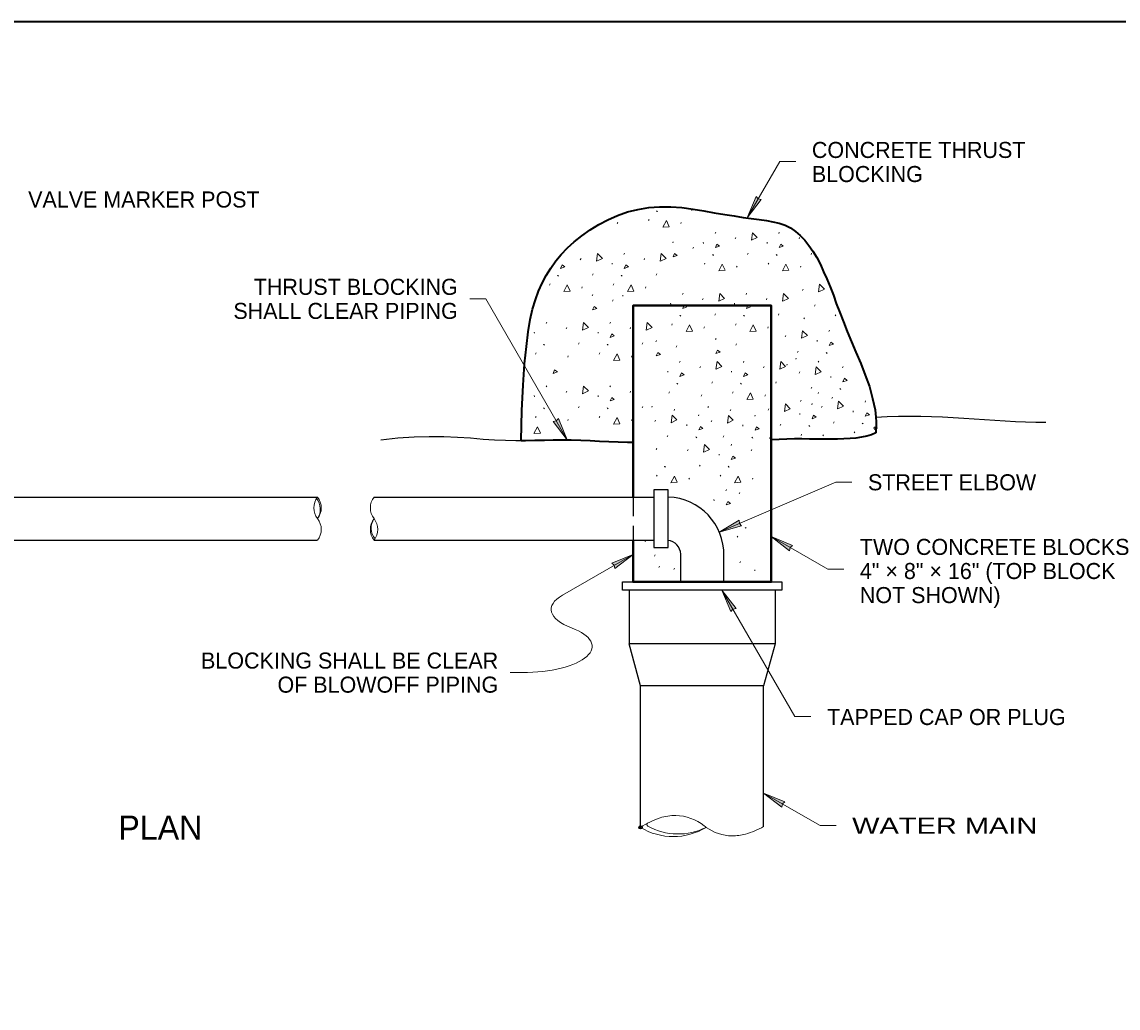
# Model space of a CAD drawing. Extents: x 99860 to 103153, y 99998 to 102077.
# Drawn here: x 100960 to 102052, y 101093 to 102076 of the extents above; entities that cross this region are included whole.
import ezdxf
from ezdxf.enums import TextEntityAlignment as Align

# ---------------------------------------------------------------- set-up
doc = ezdxf.new("R2010")
doc.units = 0
doc.header["$LTSCALE"] = 6.4
doc.header["$PDMODE"] = 32
doc.header["$PDSIZE"] = 3.2
doc.linetypes.add('MEDIUM_DASHED', pattern=[4.5, 3, -1.5])
for name, color, linetype, lineweight in [('1', 7, 'Continuous', 13), ('10', 7, 'Continuous', 13), ('11', 7, 'Continuous', 13), ('14', 7, 'Continuous', 13), ('15', 7, 'Continuous', 13), ('17', 7, 'Continuous', 35), ('20', 7, 'Continuous', 13), ('6', 7, 'Continuous', 25)]:
    doc.layers.add(name, color=color, linetype=linetype, lineweight=lineweight)

msp = doc.modelspace()

# ---------------------------------------------------------------- hatches: boundary and pattern name
at = {"layer": '15'}
for points in [[(101682.738, 101880.169), (101696.737, 101898.447), (101693.623, 101899.023), (101691.567, 101901.432)], [(101503.421, 101659.019), (101494.591, 101680.282), (101492.534, 101677.875), (101489.421, 101677.297)], [(101654.935, 101567.093), (101677.104, 101573.307), (101674.961, 101575.638), (101674.761, 101578.798)], [(101706.748, 101562.481), (101728.011, 101553.651), (101725.604, 101551.594), (101725.026, 101548.481)], [(101569.028, 101544.809), (101547.765, 101535.979), (101550.172, 101533.922), (101550.75, 101530.809)], [(101657.637, 101509.057), (101671.636, 101490.779), (101668.522, 101490.203), (101666.466, 101487.794)], [(101699.038, 101306.944), (101720.301, 101298.114), (101717.894, 101296.057), (101717.316, 101292.944)]]:
    msp.add_hatch(color=256, dxfattribs=at).paths.add_polyline_path(points)

# ---------------------------------------------------------------- linework, layer by layer
at = {"layer": '1'}
for p, q in [((101592.401, 101887.257), (101592.963, 101886.532)), ((101592.963, 101886.969), (101593.413, 101886.282)), ((101627.513, 101887.257), (101627.926, 101888.557)), ((101553.176, 101874.469), (101553.751, 101875.607)), ((101584.563, 101877.444), (101585.138, 101878.569)), ((101616.713, 101874.469), (101617.126, 101875.607)), ((101650.788, 101864.582), (101651.351, 101865.844)), ((101670.838, 101859.182), (101671.563, 101860.482)), ((101714.313, 101864.582), (101714.763, 101865.844)), ((101734.501, 101859.182), (101734.901, 101860.482)), ((101608.563, 101855.207), (101609.138, 101856.469)), ((101628.613, 101849.807), (101629.338, 101851.107)), ((101639.001, 101855.932), (101639.163, 101854.794)), ((101702.513, 101855.932), (101702.513, 101854.794)), ((101516.426, 101838.382), (101517.151, 101839.669)), ((101548.088, 101835.119), (101548.088, 101833.982)), ((101559.901, 101843.782), (101560.351, 101845.044)), ((101580.088, 101838.382), (101580.488, 101839.669)), ((101640.138, 101834.019), (101640.713, 101835.157)), ((101648.101, 101843.844), (101648.513, 101843.119)), ((101648.513, 101843.557), (101649.076, 101842.857)), ((101682.926, 101843.844), (101683.626, 101845.132)), ((101703.651, 101834.019), (101704.213, 101835.157)), ((101711.476, 101843.844), (101712.038, 101843.119)), ((101712.038, 101843.557), (101712.488, 101842.857)), ((101746.588, 101843.844), (101747.001, 101845.132)), ((101528.513, 101823.032), (101529.213, 101824.319)), ((101592.176, 101823.032), (101592.588, 101824.319)), ((101672.251, 101831.057), (101672.826, 101832.182)), ((101735.788, 101831.057), (101736.201, 101832.182)), ((101485.726, 101813.207), (101486.301, 101814.344)), ((101493.688, 101823.032), (101494.101, 101822.307)), ((101494.101, 101822.744), (101494.663, 101822.057)), ((101549.226, 101813.207), (101549.801, 101814.344)), ((101557.063, 101823.032), (101557.626, 101822.307)), ((101557.626, 101822.744), (101558.076, 101822.057)), ((101517.838, 101810.244), (101518.413, 101811.382)), ((101528.388, 101802.507), (101528.963, 101803.769)), ((101558.826, 101803.232), (101558.988, 101802.094)), ((101581.376, 101810.244), (101581.788, 101811.382)), ((101618.226, 101803.957), (101618.801, 101805.219)), ((101681.763, 101803.957), (101682.201, 101805.219)), ((101737.751, 101807.719), (101738.476, 101809.007)), ((101548.438, 101797.107), (101549.163, 101798.394)), ((101606.451, 101795.307), (101606.613, 101794.169)), ((101638.276, 101798.557), (101639.001, 101799.857)), ((101669.951, 101795.307), (101669.951, 101794.169)), ((101701.938, 101798.557), (101702.351, 101799.857)), ((101749.838, 101792.369), (101750.538, 101793.669)), ((101615.538, 101783.207), (101615.951, 101782.482)), ((101615.951, 101782.932), (101616.526, 101782.232)), ((101650.376, 101783.207), (101651.063, 101784.507)), ((101678.926, 101783.207), (101679.488, 101782.482)), ((101679.488, 101782.932), (101679.926, 101782.232)), ((101714.038, 101783.207), (101714.438, 101784.507)), ((101739.163, 101779.582), (101739.738, 101780.719)), ((101770.563, 101782.544), (101771.126, 101783.682)), ((101482.413, 101775.032), (101482.976, 101776.294)), ((101502.463, 101769.632), (101503.188, 101770.932)), ((101545.951, 101775.032), (101546.388, 101776.294)), ((101566.126, 101769.632), (101566.538, 101770.932)), ((101607.588, 101773.394), (101608.151, 101774.532)), ((101639.701, 101770.419), (101640.263, 101771.557)), ((101671.088, 101773.394), (101671.651, 101774.532)), ((101703.238, 101770.419), (101703.651, 101771.557)), ((101470.638, 101766.382), (101470.788, 101765.244)), ((101534.138, 101766.382), (101534.138, 101765.244)), ((101651.263, 101758.832), (101651.826, 101760.094)), ((101720.701, 101761.519), (101721.426, 101762.807)), ((101764.176, 101766.919), (101764.626, 101768.182)), ((101479.726, 101754.282), (101480.138, 101753.557)), ((101480.138, 101754.007), (101480.713, 101753.307)), ((101514.563, 101754.282), (101515.251, 101755.582)), ((101543.101, 101754.282), (101543.676, 101753.557)), ((101543.676, 101754.007), (101544.113, 101753.307)), ((101578.213, 101754.282), (101578.626, 101755.582)), ((101591.863, 101756.682), (101592.426, 101757.944)), ((101611.913, 101751.282), (101612.638, 101752.582)), ((101671.313, 101753.432), (101672.038, 101754.732)), ((101752.363, 101758.269), (101752.363, 101757.132)), ((101471.776, 101744.469), (101472.338, 101745.607)), ((101503.888, 101741.494), (101504.451, 101742.632)), ((101535.276, 101744.469), (101535.838, 101745.607)), ((101567.413, 101741.494), (101567.826, 101742.632)), ((101615.413, 101736.132), (101615.988, 101737.394)), ((101678.951, 101736.132), (101679.388, 101737.394)), ((101731.213, 101739.419), (101731.626, 101740.544)), ((101732.788, 101746.169), (101733.488, 101747.469)), ((101753.501, 101736.344), (101754.076, 101737.482)), ((101761.338, 101746.169), (101761.901, 101745.444)), ((101761.901, 101745.882), (101762.351, 101745.194)), ((101603.638, 101727.482), (101603.801, 101726.344)), ((101635.463, 101730.732), (101636.201, 101732.019)), ((101667.138, 101727.482), (101667.138, 101726.344)), ((101699.126, 101730.732), (101699.538, 101732.019)), ((101722.113, 101733.382), (101722.688, 101734.519)), ((101734.401, 101725.394), (101735.126, 101726.682)), ((101777.888, 101730.794), (101778.326, 101732.057)), ((101612.738, 101715.382), (101613.138, 101714.657)), ((101613.138, 101715.094), (101613.713, 101714.407)), ((101647.563, 101715.382), (101648.263, 101716.682)), ((101676.113, 101715.382), (101676.676, 101714.657)), ((101676.676, 101715.094), (101677.126, 101714.407)), ((101711.226, 101715.382), (101711.638, 101716.682)), ((101766.076, 101722.144), (101766.076, 101721.007)), ((101482.413, 101711.694), (101482.976, 101712.957)), ((101502.463, 101706.294), (101503.188, 101707.582)), ((101545.951, 101711.694), (101546.388, 101712.957)), ((101566.126, 101706.294), (101566.538, 101707.582)), ((101604.776, 101705.557), (101605.338, 101706.694)), ((101668.276, 101705.557), (101668.851, 101706.694)), ((101746.501, 101710.044), (101747.188, 101711.344)), ((101753.501, 101705.119), (101753.913, 101706.257)), ((101775.038, 101710.044), (101775.613, 101709.319)), ((101775.613, 101709.757), (101776.051, 101709.069)), ((101470.638, 101703.032), (101470.788, 101701.894)), ((101534.138, 101703.032), (101534.138, 101701.894)), ((101636.888, 101702.594), (101637.463, 101703.732)), ((101700.426, 101702.594), (101700.838, 101703.732)), ((101735.826, 101697.257), (101736.388, 101698.394)), ((101747.101, 101693.969), (101747.538, 101695.232)), ((101767.213, 101700.219), (101767.776, 101701.357)), ((101800.176, 101696.494), (101800.613, 101697.757)), ((101471.776, 101681.119), (101472.338, 101682.257)), ((101479.726, 101690.944), (101480.138, 101690.219)), ((101480.138, 101690.657), (101480.713, 101689.957)), ((101514.563, 101690.944), (101515.251, 101692.232)), ((101535.276, 101681.119), (101535.838, 101682.257)), ((101543.101, 101690.944), (101543.676, 101690.219)), ((101543.676, 101690.657), (101544.113, 101689.957)), ((101578.213, 101690.944), (101578.626, 101692.232)), ((101587.601, 101691.419), (101588.013, 101692.557)), ((101609.888, 101688.357), (101610.463, 101689.494)), ((101634.263, 101682.794), (101634.713, 101684.057)), ((101643.651, 101691.069), (101644.063, 101692.207)), ((101665.938, 101688.007), (101666.513, 101689.144)), ((101690.313, 101682.444), (101690.763, 101683.707)), ((101703.613, 101688.569), (101704.338, 101689.869)), ((101735.288, 101685.319), (101735.288, 101684.182)), ((101756.701, 101691.094), (101757.426, 101692.394)), ((101788.363, 101687.844), (101788.363, 101686.707)), ((101503.888, 101678.157), (101504.451, 101679.294)), ((101567.413, 101678.157), (101567.826, 101679.294)), ((101590.788, 101677.394), (101591.513, 101678.694)), ((101622.463, 101674.144), (101622.463, 101673.007)), ((101646.838, 101677.044), (101647.563, 101678.344)), ((101678.513, 101673.794), (101678.513, 101672.657)), ((101715.713, 101673.232), (101716.401, 101674.519)), ((101744.251, 101673.232), (101744.826, 101672.494)), ((101744.826, 101672.944), (101745.263, 101672.244)), ((101768.788, 101675.757), (101769.488, 101677.044)), ((101797.338, 101675.757), (101797.901, 101675.032)), ((101797.901, 101675.469), (101798.351, 101674.769)), ((101602.876, 101662.044), (101603.576, 101663.344)), ((101631.426, 101662.044), (101632.001, 101661.319)), ((101632.001, 101661.769), (101632.438, 101661.069)), ((101658.926, 101661.707), (101659.626, 101662.994)), ((101687.476, 101661.707), (101688.051, 101660.969)), ((101688.051, 101661.419), (101688.488, 101660.719)), ((101705.038, 101660.432), (101705.601, 101661.569)), ((101736.426, 101663.407), (101736.988, 101664.544)), ((101758.113, 101662.969), (101758.688, 101664.107)), ((101789.501, 101665.932), (101790.076, 101667.069)), ((101592.213, 101649.257), (101592.776, 101650.394)), ((101666.638, 101653.332), (101667.076, 101654.594)), ((101623.151, 101647.932), (101623.876, 101649.232)), ((101654.826, 101644.682), (101654.826, 101643.544)), ((101686.813, 101647.932), (101687.226, 101649.232)), ((101600.413, 101632.582), (101600.826, 101631.857)), ((101600.826, 101632.307), (101601.401, 101631.607)), ((101635.251, 101632.582), (101635.938, 101633.882)), ((101663.788, 101632.582), (101664.363, 101631.857)), ((101664.363, 101632.307), (101664.801, 101631.607)), ((101592.463, 101622.769), (101593.026, 101623.907)), ((101624.576, 101619.794), (101625.138, 101620.932)), ((101655.963, 101622.769), (101656.526, 101623.907)), ((101688.113, 101619.794), (101688.513, 101620.932)), ((101661.463, 101608.119), (101662.026, 101609.382)), ((101674.726, 101605.144), (101675.288, 101606.407)), ((101649.676, 101599.457), (101649.838, 101598.319)), ((101672.788, 101561.944), (101673.363, 101563.082)), ((101680.751, 101571.769), (101681.163, 101571.044)), ((101681.163, 101571.482), (101681.726, 101570.794)), ((101590.251, 101543.007), (101590.951, 101544.294)), ((101594.551, 101531.882), (101595.238, 101533.182)), ((101609.538, 101529.807), (101610.238, 101531.094)), ((101675.351, 101536.432), (101675.926, 101537.569)), ((101690.251, 101529.582), (101690.413, 101528.444))]:
    msp.add_line(p, q, dxfattribs=at)
at = {"layer": '1', "lineweight": 25}
msp.add_line((101581.413, 101557.557), (101581.413, 101558.919), dxfattribs=at)
at = {"layer": '1', "lineweight": 35}
msp.add_lwpolyline([(99862, 99999.5), (103151, 99999.5), (103151, 102075.5), (99862, 102075.5)], close=True, dxfattribs=at)
at = {"layer": '1'}
for points in [[(101598.776, 101870.932), (101602.338, 101877.594), (101605.026, 101871.344), (101598.938, 101870.932)], [(101687.038, 101857.894), (101688.051, 101865.444), (101692.851, 101860.607), (101687.163, 101857.894)], [(101532.626, 101837.082), (101533.626, 101844.632), (101538.426, 101839.794), (101532.751, 101837.082)], [(101596.151, 101837.082), (101597.138, 101844.632), (101601.963, 101839.794), (101596.276, 101837.082)], [(101654.351, 101827.519), (101657.926, 101834.182), (101660.763, 101827.919), (101654.513, 101827.519)], [(101717.851, 101827.519), (101721.426, 101834.182), (101724.113, 101827.919), (101718.013, 101827.519)], [(101499.938, 101806.707), (101503.501, 101813.369), (101506.351, 101807.119), (101500.101, 101806.707)], [(101563.438, 101806.707), (101567.013, 101813.369), (101569.688, 101807.119), (101563.601, 101806.707)], [(101753.951, 101806.419), (101754.963, 101813.969), (101759.763, 101809.132), (101754.076, 101806.419)], [(101654.476, 101797.269), (101655.488, 101804.807), (101660.288, 101799.982), (101654.601, 101797.269)], [(101718.013, 101797.269), (101718.988, 101804.807), (101723.826, 101799.982), (101718.138, 101797.269)], [(101518.663, 101768.344), (101519.676, 101775.882), (101524.476, 101771.057), (101518.788, 101768.344)], [(101582.201, 101768.344), (101583.176, 101775.882), (101588.013, 101771.057), (101582.326, 101768.344)], [(101621.801, 101766.882), (101625.363, 101773.544), (101628.201, 101767.294), (101621.951, 101766.882)], [(101685.301, 101766.882), (101688.863, 101773.544), (101691.551, 101767.294), (101685.451, 101766.882)], [(101736.901, 101760.219), (101737.901, 101767.769), (101742.701, 101762.944), (101737.026, 101760.219)], [(101549.488, 101737.957), (101553.051, 101744.619), (101555.738, 101738.369), (101549.638, 101737.957)], [(101651.663, 101729.432), (101652.676, 101736.982), (101657.476, 101732.144), (101651.801, 101729.432)], [(101715.201, 101729.432), (101716.176, 101736.982), (101721.013, 101732.144), (101715.326, 101729.432)], [(101750.601, 101724.094), (101751.613, 101731.644), (101756.413, 101726.819), (101750.726, 101724.094)], [(101518.663, 101704.994), (101519.676, 101712.544), (101524.476, 101707.707), (101518.788, 101704.994)], [(101682.488, 101699.057), (101686.051, 101705.719), (101688.738, 101699.469), (101682.651, 101699.057)], [(101719.813, 101687.282), (101720.826, 101694.832), (101725.626, 101689.994), (101719.938, 101687.282)], [(101772.888, 101689.807), (101773.901, 101697.357), (101778.701, 101692.519), (101773.026, 101689.807)], [(101606.988, 101676.094), (101608.001, 101683.644), (101612.801, 101678.819), (101607.113, 101676.094)], [(101663.038, 101675.757), (101664.051, 101683.294), (101668.851, 101678.469), (101663.163, 101675.757)], [(101470.242, 101665.357), (101473.817, 101672.019), (101476.654, 101665.769), (101470.404, 101665.357)], [(101549.488, 101674.619), (101553.051, 101681.282), (101555.738, 101675.032), (101549.638, 101674.619)], [(101639.351, 101646.644), (101640.363, 101654.182), (101645.163, 101649.357), (101639.476, 101646.644)], [(101606.676, 101616.257), (101610.238, 101622.919), (101613.076, 101616.669), (101606.826, 101616.257)], [(101670.176, 101616.257), (101673.738, 101622.919), (101676.426, 101616.669), (101670.326, 101616.257)]]:
    msp.add_lwpolyline(points, dxfattribs=at)
for points in [[(101651.101, 101850.657), (101652.651, 101854.069), (101655.326, 101852.082)], [(101714.601, 101850.657), (101716.151, 101854.069), (101718.738, 101852.082)], [(101608.876, 101841.282), (101610.426, 101844.694), (101613.113, 101842.707)], [(101496.688, 101829.857), (101498.238, 101833.257), (101500.913, 101831.269)], [(101560.188, 101829.857), (101561.738, 101833.257), (101564.326, 101831.269)], [(101528.701, 101788.582), (101530.251, 101791.994), (101532.938, 101789.994)], [(101618.538, 101790.032), (101620.088, 101793.444), (101622.776, 101791.457)], [(101682.051, 101790.032), (101683.588, 101793.444), (101686.188, 101791.457)], [(101546.226, 101761.107), (101547.776, 101764.519), (101550.363, 101762.532)], [(101651.576, 101744.907), (101653.126, 101748.319), (101655.801, 101746.332)], [(101764.463, 101752.994), (101766.013, 101756.407), (101768.601, 101754.407)], [(101592.176, 101742.757), (101593.726, 101746.169), (101596.413, 101744.182)], [(101489.339, 101725.201), (101490.889, 101728.613), (101493.576, 101726.626)], [(101615.738, 101722.207), (101617.276, 101725.619), (101619.963, 101723.619)], [(101679.238, 101722.207), (101680.788, 101725.619), (101683.376, 101723.619)], [(101778.163, 101716.869), (101779.713, 101720.282), (101782.301, 101718.282)], [(101546.226, 101697.757), (101547.776, 101701.169), (101550.363, 101699.182)], [(101747.376, 101680.044), (101748.926, 101683.457), (101751.513, 101681.469)], [(101800.463, 101682.569), (101802.013, 101685.982), (101804.601, 101683.994)], [(101634.551, 101668.869), (101636.101, 101672.282), (101638.688, 101670.294)], [(101690.601, 101668.519), (101692.151, 101671.932), (101694.738, 101669.944)], [(101666.926, 101639.407), (101668.463, 101642.819), (101671.051, 101640.832)], [(101661.776, 101594.194), (101663.326, 101597.594), (101666.001, 101595.607)]]:
    msp.add_lwpolyline(points, close=True, dxfattribs=at)
at = {"layer": '10'}
msp.add_point((101810.601, 101670.482), dxfattribs=at)
at = {"layer": '11'}
msp.add_arc((101584.483, 101275.506), 1.699, 130.64235, 246.19532, dxfattribs=at)
at = {"layer": '14'}
msp.add_line((101446.631, 101426.99), (101458.631, 101426.99), dxfattribs=at)
for centre, start_param, end_param in [((101557.025, 101489.979), 5.70716111, 7.06862381), ((101458.631, 101453.081), 1.57079633, 3.92695896)]:
    msp.add_ellipse(centre, major_axis=(-69.576, 0), ratio=0.375, start_param=start_param, end_param=end_param, dxfattribs=at)
at = {"layer": '15'}
for p, q in [((101682.738, 101880.169), (101715.239, 101936.461)), ((101715.239, 101936.461), (101731.238, 101936.461)), ((101406.327, 101799.477), (101422.328, 101799.477)), ((101503.421, 101659.019), (101422.328, 101799.477)), ((101654.935, 101567.093), (101771.104, 101616.662)), ((101771.104, 101616.662), (101787.104, 101616.662)), ((101706.748, 101562.481), (101763.04, 101529.981)), ((101569.028, 101544.809), (101498.676, 101504.191)), ((101763.04, 101529.981), (101779.038, 101529.981)), ((101657.637, 101509.057), (101730.334, 101383.143)), ((101730.334, 101383.143), (101746.337, 101383.143)), ((101699.038, 101306.944), (101755.33, 101274.444)), ((101755.33, 101274.444), (101771.33, 101274.444))]:
    msp.add_line(p, q, dxfattribs=at)
for points in [[(101682.738, 101880.169), (101696.737, 101898.447), (101693.623, 101899.023), (101691.567, 101901.432)], [(101503.421, 101659.019), (101494.591, 101680.282), (101492.534, 101677.875), (101489.421, 101677.297)], [(101654.935, 101567.093), (101677.104, 101573.307), (101674.961, 101575.638), (101674.761, 101578.798)], [(101706.748, 101562.481), (101728.011, 101553.651), (101725.604, 101551.594), (101725.026, 101548.481)], [(101569.028, 101544.809), (101547.765, 101535.979), (101550.172, 101533.922), (101550.75, 101530.809)], [(101657.637, 101509.057), (101671.636, 101490.779), (101668.522, 101490.203), (101666.466, 101487.794)], [(101699.038, 101306.944), (101720.301, 101298.114), (101717.894, 101296.057), (101717.316, 101292.944)]]:
    msp.add_lwpolyline(points, close=True, dxfattribs=at)
at = {"layer": '17', "linetype": 'MEDIUM_DASHED', "lineweight": 25}
msp.add_line((101569.028, 101601.957), (101569.028, 101558.919), dxfattribs=at)
at = {"layer": '17'}
for points in [[(101457.651, 101658.294), (101458.351, 101688.382), (101459.451, 101713.519), (101460.876, 101734.707), (101462.676, 101751.919), (101464.451, 101766.607), (101466.626, 101778.857), (101468.738, 101789.207), (101471.651, 101798.594), (101474.838, 101807.182), (101478.401, 101815.044), (101482.376, 101822.932), (101487.051, 101830.107), (101492.076, 101837.269), (101497.438, 101843.782), (101503.538, 101850.182), (101510.388, 101856.319), (101517.901, 101862.407), (101526.151, 101868.182), (101534.763, 101873.557), (101543.738, 101878.194), (101553.401, 101882.494), (101563.501, 101886.057), (101573.863, 101888.582), (101584.601, 101890.382), (101595.401, 101891.107), (101606.513, 101891.107), (101617.626, 101890.382), (101628.776, 101888.969), (101639.513, 101887.169), (101649.901, 101885.369), (101660.351, 101883.594), (101669.663, 101882.082), (101678.601, 101880.694), (101686.876, 101879.644), (101694.738, 101878.507), (101701.938, 101877.507), (101708.376, 101876.394), (101714.476, 101874.944), (101720.576, 101872.794), (101725.976, 101870.332), (101730.988, 101866.732), (101735.638, 101862.757), (101740.276, 101858.082), (101744.251, 101852.719), (101748.238, 101846.994), (101752.151, 101840.557), (101755.751, 101833.707), (101758.963, 101826.532), (101762.188, 101819.369), (101765.413, 101811.444), (101768.663, 101803.232), (101771.501, 101794.994), (101775.101, 101786.019), (101778.701, 101776.707), (101782.338, 101767.007), (101786.601, 101756.594), (101790.926, 101746.207), (101795.888, 101735.057), (101800.238, 101723.557), (101804.538, 101712.094), (101807.751, 101700.257), (101810.276, 101688.794), (101811.013, 101681.632)], [(101811.013, 101681.632), (101811.326, 101676.919), (101811.013, 101665.832)], [(101457.651, 101658.294), (101461.951, 101658.294), (101471.238, 101658.669), (101480.613, 101658.669), (101489.551, 101659.019), (101498.513, 101659.019), (101507.513, 101659.019), (101516.863, 101658.669), (101526.151, 101658.294), (101535.501, 101657.594), (101544.776, 101657.219), (101554.151, 101656.869), (101563.501, 101656.494), (101569.028, 101656.494)]]:
    msp.add_lwpolyline(points, dxfattribs=at)
at = {"layer": '17', "lineweight": 40}
msp.add_lwpolyline([(101569.028, 101601.957), (101569.028, 101792.734), (101706.748, 101792.734), (101706.748, 101517.294), (101569.028, 101517.294), (101569.028, 101558.919)], dxfattribs=at)
at = {"layer": '17', "lineweight": 25}
msp.add_lwpolyline([(101317.738, 101659.019), (101334.563, 101660.819), (101350.763, 101661.857), (101365.763, 101662.269), (101380.538, 101662.269), (101394.126, 101661.507), (101407.063, 101660.819), (101419.638, 101659.707), (101431.063, 101659.019), (101441.838, 101658.669), (101452.251, 101658.294), (101457.651, 101658.294)], dxfattribs=at)
msp.add_open_spline([(101811.013, 101681.632), (101872.013, 101685.569), (101926.838, 101676.607), (101980.326, 101676.607)], degree=3, dxfattribs=at)
at = {"layer": '17'}
msp.add_open_spline([(101811.013, 101665.832), (101788.817, 101655.353), (101747.926, 101661.873), (101706.748, 101659.037)], degree=3, dxfattribs=at)
at = {"layer": '6'}
for p, q in [((101603.988, 101609.157), (101589.651, 101609.157)), ((101589.651, 101609.157), (101589.651, 101551.744)), ((101603.988, 101551.744), (101603.988, 101609.157)), ((100852.438, 101601.957), (101254.613, 101601.957)), ((101310.913, 101601.957), (101589.651, 101601.957)), ((100852.438, 101558.919), (101254.201, 101558.919)), ((101310.913, 101558.919), (101589.651, 101558.919)), ((101589.651, 101551.744), (101603.988, 101551.744)), ((101616.488, 101517.294), (101616.488, 101545.196)), ((101659.563, 101517.294), (101659.563, 101543.632)), ((101565.276, 101509.057), (101565.276, 101455.632)), ((101710.563, 101509.057), (101710.563, 101455.632)), ((101710.563, 101455.632), (101565.276, 101455.632)), ((101576.388, 101413.657), (101565.276, 101455.632)), ((101710.563, 101455.632), (101699.038, 101413.657)), ((101699.038, 101413.657), (101576.388, 101413.657)), ((101576.388, 101272.642), (101576.388, 101413.657)), ((101699.038, 101273.755), (101699.038, 101413.657))]:
    msp.add_line(p, q, dxfattribs=at)
msp.add_lwpolyline([(101717.351, 101517.294), (101717.351, 101509.057), (101558.426, 101509.057), (101558.426, 101517.294)], close=True, dxfattribs=at)
at = {"layer": '6', "lineweight": 13}
for centre, radius, start, end in [((101268.474, 101591.195), 17.548, 142.17249, 217.82751), ((101240.216, 101589.677), 17.109, 327.29748, 38.85332), ((101240.753, 101591.195), 17.548, 322.17249, 37.82751), ((101324.774, 101591.205), 17.548, 142.17249, 217.82751), ((101240.753, 101569.671), 17.548, 322.17249, 37.82751), ((101324.774, 101569.681), 17.548, 142.17249, 217.82751), ((101325.238, 101571.039), 17.136, 146.71491, 218.80016), ((101297.053, 101569.681), 17.548, 322.17249, 37.82751), ((101623.057, 101201.496), 85.114, 108.59987, 123.18182), ((101610.582, 101238.564), 46.004, 88.71938, 108.59987), ((101610.566, 101237.812), 46.756, 51.10871, 88.71937), ((101609.12, 101326.009), 62.484, 238.50198, 301.54708), ((101613.934, 101328.286), 62.133, 240.98536, 296.66005), ((101668.018, 101309.035), 44.751, 231.10871, 234.15596), ((101668.018, 101309.035), 44.751, 234.15596, 269.58481), ((101657.68, 101348.357), 85.508, 285.77825, 298.99002), ((101668.037, 101311.701), 47.417, 269.5848, 285.77825)]:
    msp.add_arc(centre, radius, start, end, dxfattribs=at)
at = {"layer": '6'}
for radius, start, end in [(57.396, 359.0671, 87.98067), (14.359, 2.51368, 82.61837)]:
    msp.add_arc((101602.144, 101544.567), radius, start, end, dxfattribs=at)
msp.add_point((101576.474, 101272.731), dxfattribs=at)

# ---------------------------------------------------------------- texts
at = {"layer": '20'}
for s, p in [('CONCRETE THRUST', (101747.229, 101939.902)), ('BLOCKING', (101747.229, 101915.902)), ('VALVE MARKER POST', (100966.242, 101890.516)), ('STREET ELBOW', (101803.104, 101608.662)), ('TWO CONCRETE BLOCKS', (101795.038, 101544.259)), ('4" × 8" × 16" (TOP BLOCK', (101795.038, 101520.259)), ('NOT SHOWN)', (101795.038, 101496.259)), ('TAPPED CAP OR PLUG', (101762.337, 101374.741))]:
    msp.add_text(s, height=16, dxfattribs=at).set_placement(p)
for s, p in [('THRUST BLOCKING', (101394.331, 101803.477)), ('SHALL CLEAR PIPING', (101394.331, 101779.477)), ('BLOCKING SHALL BE CLEAR', (101434.636, 101430.99)), ('OF BLOWOFF PIPING', (101434.636, 101406.99))]:
    msp.add_text(s, height=16, dxfattribs=at).set_placement(p, align=Align.RIGHT)
msp.add_text('PLAN', height=24, dxfattribs=at).set_placement((101097.999, 101260.501), align=Align.CENTER)
at = {"layer": '20', "width": 1.35}
msp.add_text('WATER MAIN', height=16, dxfattribs=at).set_placement((101787.33, 101266.444))

doc.saveas('drawing.dxf')
